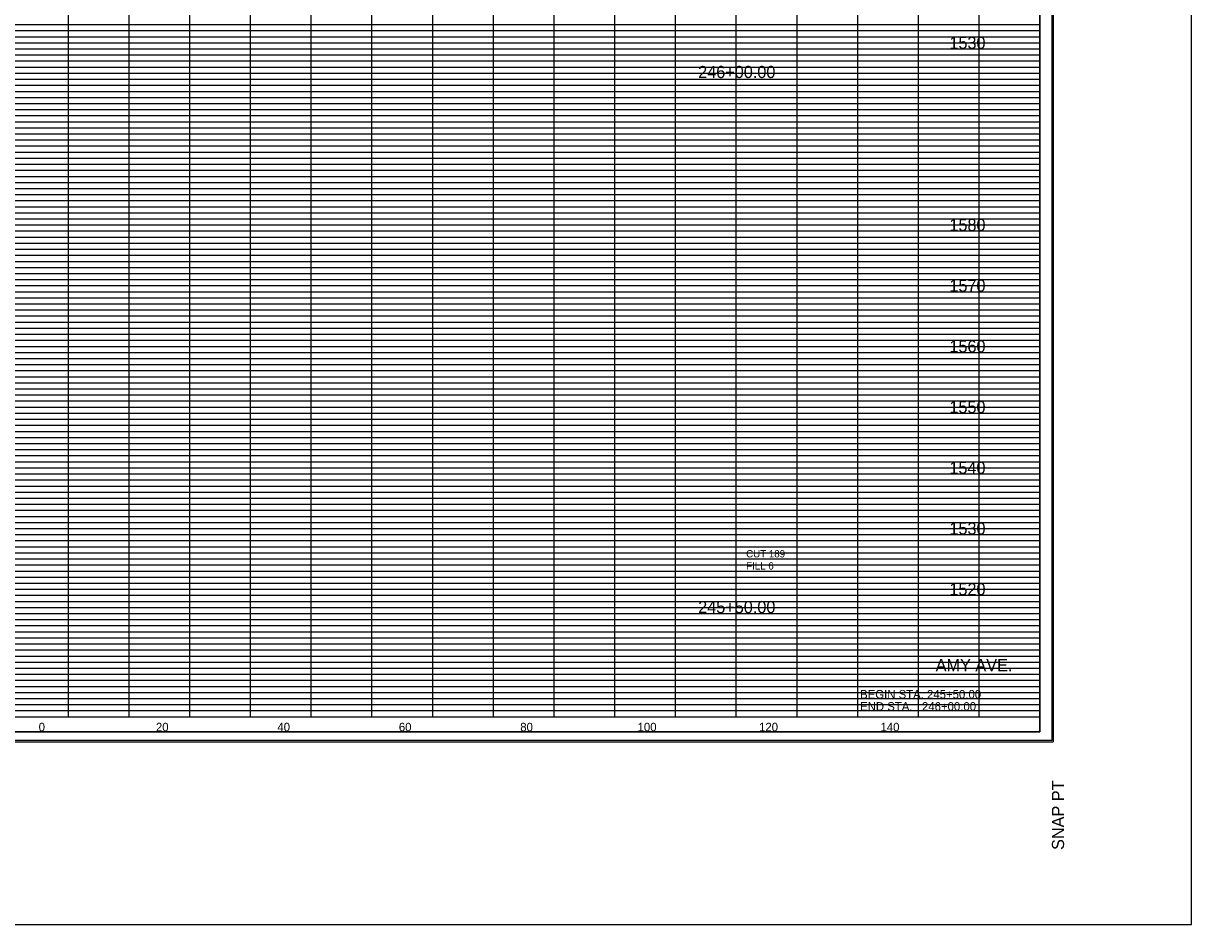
# Model space of a CAD drawing. Extents: x 955 to 1375, y 1248 to 3657.
# Drawn here: x 1152.6 to 1345, y 1505.8 to 1654.2 of the extents above; entities that cross this region are included whole.
import ezdxf

# ---------------------------------------------------------------- set-up
doc = ezdxf.new("R2010")
doc.units = 0
for name, color, linetype in [('DESIGN - SHEET - Corner Text', 7, 'Continuous'), ('DESIGN - SHEET - Light Grid', 7, 'Continuous'), ('DESIGN - SHEET - Linework', 7, 'Continuous'), ('DESIGN - SHEET - Plot Shape', 7, 'Continuous'), ('DESIGN - TYPICAL - Text', 7, 'Continuous'), ('DESIGN - UTILITIES - Cable (Overhead) with Text', 7, 'Continuous'), ('SURVEY - NON-TRANSPORTATION - Features Text', 7, 'Continuous')]:
    doc.layers.add(name, color=color, linetype=linetype)

# ---------------------------------------------------------------- blocks, each defined once
blk = doc.blocks.new('XSTSHT')
at = {"layer": 'DESIGN - SHEET - Light Grid'}
for p, q in [((8, 11.4), (16, 11.4)), ((16, 11.4), (24, 11.4)), ((24, 11.4), (32, 11.4)), ((8, 11.3), (16, 11.3)), ((8, 11.2), (16, 11.2)), ((16, 11.3), (24, 11.3)), ((16, 11.2), (24, 11.2)), ((24, 11.3), (32, 11.3)), ((24, 11.2), (32, 11.2)), ((8, 11.1), (16, 11.1)), ((16, 11.1), (24, 11.1)), ((24, 11.1), (32, 11.1)), ((8, 10.9), (16, 10.9)), ((8, 10.8), (16, 10.8)), ((16, 10.9), (24, 10.9)), ((16, 10.8), (24, 10.8)), ((24, 10.9), (32, 10.9)), ((24, 10.8), (32, 10.8)), ((8, 10.7), (16, 10.7)), ((8, 10.6), (16, 10.6)), ((16, 10.7), (24, 10.7)), ((16, 10.6), (24, 10.6)), ((24, 10.7), (32, 10.7)), ((24, 10.6), (32, 10.6)), ((8, 10.5), (16, 10.5)), ((8, 10.4), (16, 10.4)), ((16, 10.5), (24, 10.5)), ((16, 10.4), (24, 10.4)), ((24, 10.5), (32, 10.5)), ((24, 10.4), (32, 10.4)), ((8, 10.3), (16, 10.3)), ((8, 10.2), (16, 10.2)), ((16, 10.3), (24, 10.3)), ((16, 10.2), (24, 10.2)), ((24, 10.3), (32, 10.3)), ((24, 10.2), (32, 10.2)), ((8, 10.1), (16, 10.1)), ((16, 10.1), (24, 10.1)), ((24, 10.1), (32, 10.1)), ((8, 9.9), (16, 9.9)), ((16, 9.9), (24, 9.9)), ((24, 9.9), (32, 9.9)), ((8, 9.8), (16, 9.8)), ((8, 9.7), (16, 9.7)), ((16, 9.8), (24, 9.8)), ((16, 9.7), (24, 9.7)), ((24, 9.8), (32, 9.8)), ((24, 9.7), (32, 9.7)), ((8, 9.6), (16, 9.6)), ((8, 9.5), (16, 9.5)), ((16, 9.6), (24, 9.6)), ((16, 9.5), (24, 9.5)), ((24, 9.6), (32, 9.6)), ((24, 9.5), (32, 9.5)), ((8, 9.4), (16, 9.4)), ((8, 9.3), (16, 9.3)), ((16, 9.4), (24, 9.4)), ((16, 9.3), (24, 9.3)), ((24, 9.4), (32, 9.4)), ((24, 9.3), (32, 9.3)), ((8, 9.2), (16, 9.2)), ((8, 9.1), (16, 9.1)), ((16, 9.2), (24, 9.2)), ((16, 9.1), (24, 9.1)), ((24, 9.2), (32, 9.2)), ((24, 9.1), (32, 9.1)), ((8, 8.9), (16, 8.9)), ((16, 8.9), (24, 8.9)), ((24, 8.9), (32, 8.9)), ((8, 8.8), (16, 8.8)), ((8, 8.7), (16, 8.7)), ((16, 8.8), (24, 8.8)), ((16, 8.7), (24, 8.7)), ((24, 8.8), (32, 8.8)), ((24, 8.7), (32, 8.7)), ((8, 8.6), (16, 8.6)), ((8, 8.5), (16, 8.5)), ((16, 8.6), (24, 8.6)), ((16, 8.5), (24, 8.5)), ((24, 8.6), (32, 8.6)), ((24, 8.5), (32, 8.5)), ((8, 8.4), (16, 8.4)), ((8, 8.3), (16, 8.3)), ((16, 8.4), (24, 8.4)), ((16, 8.3), (24, 8.3)), ((24, 8.4), (32, 8.4)), ((24, 8.3), (32, 8.3)), ((8, 8.2), (16, 8.2)), ((8, 8.1), (16, 8.1)), ((16, 8.2), (24, 8.2)), ((16, 8.1), (24, 8.1)), ((24, 8.2), (32, 8.2)), ((24, 8.1), (32, 8.1)), ((8, 7.9), (16, 7.9)), ((16, 7.9), (24, 7.9)), ((24, 7.9), (32, 7.9)), ((8, 7.8), (16, 7.8)), ((8, 7.7), (16, 7.7)), ((16, 7.8), (24, 7.8)), ((16, 7.7), (24, 7.7)), ((24, 7.8), (32, 7.8)), ((24, 7.7), (32, 7.7)), ((8, 7.6), (16, 7.6)), ((16, 7.6), (24, 7.6)), ((24, 7.6), (32, 7.6)), ((8, 7.5), (16, 7.5)), ((8, 7.4), (16, 7.4)), ((16, 7.5), (24, 7.5)), ((16, 7.4), (24, 7.4)), ((24, 7.5), (32, 7.5)), ((24, 7.4), (32, 7.4)), ((8, 7.3), (16, 7.3)), ((8, 7.2), (16, 7.2)), ((16, 7.3), (24, 7.3)), ((16, 7.2), (24, 7.2)), ((24, 7.3), (32, 7.3)), ((24, 7.2), (32, 7.2)), ((8, 7.1), (16, 7.1)), ((16, 7.1), (24, 7.1)), ((24, 7.1), (32, 7.1)), ((8, 6.9), (16, 6.9)), ((8, 6.8), (16, 6.8)), ((16, 6.9), (24, 6.9)), ((16, 6.8), (24, 6.8)), ((24, 6.9), (32, 6.9)), ((24, 6.8), (32, 6.8)), ((8, 6.7), (16, 6.7)), ((8, 6.6), (16, 6.6)), ((16, 6.7), (24, 6.7)), ((16, 6.6), (24, 6.6)), ((24, 6.7), (32, 6.7)), ((24, 6.6), (32, 6.6)), ((8, 6.5), (16, 6.5)), ((8, 6.4), (16, 6.4)), ((16, 6.5), (24, 6.5)), ((16, 6.4), (24, 6.4)), ((24, 6.5), (32, 6.5)), ((24, 6.4), (32, 6.4)), ((8, 6.3), (16, 6.3)), ((8, 6.2), (16, 6.2)), ((16, 6.3), (24, 6.3)), ((16, 6.2), (24, 6.2)), ((24, 6.3), (32, 6.3)), ((24, 6.2), (32, 6.2)), ((8, 6.1), (16, 6.1)), ((16, 6.1), (24, 6.1)), ((24, 6.1), (32, 6.1)), ((8, 5.9), (16, 5.9)), ((8, 5.8), (16, 5.8)), ((16, 5.9), (24, 5.9)), ((16, 5.8), (24, 5.8)), ((24, 5.9), (32, 5.9)), ((24, 5.8), (32, 5.8)), ((8, 5.7), (16, 5.7)), ((8, 5.6), (16, 5.6)), ((16, 5.7), (24, 5.7)), ((16, 5.6), (24, 5.6)), ((24, 5.7), (32, 5.7)), ((24, 5.6), (32, 5.6)), ((8, 5.5), (16, 5.5)), ((8, 5.4), (16, 5.4)), ((16, 5.5), (24, 5.5)), ((16, 5.4), (24, 5.4)), ((24, 5.5), (32, 5.5)), ((24, 5.4), (32, 5.4)), ((8, 5.3), (16, 5.3)), ((8, 5.2), (16, 5.2)), ((16, 5.3), (24, 5.3)), ((16, 5.2), (24, 5.2)), ((24, 5.3), (32, 5.3)), ((24, 5.2), (32, 5.2)), ((8, 5.1), (16, 5.1)), ((16, 5.1), (24, 5.1)), ((24, 5.1), (32, 5.1)), ((8, 4.9), (16, 4.9)), ((16, 4.9), (24, 4.9)), ((24, 4.9), (32, 4.9)), ((8, 4.8), (16, 4.8)), ((8, 4.7), (16, 4.7)), ((16, 4.8), (24, 4.8)), ((16, 4.7), (24, 4.7)), ((24, 4.8), (32, 4.8)), ((24, 4.7), (32, 4.7)), ((8, 4.6), (16, 4.6)), ((8, 4.5), (16, 4.5)), ((16, 4.6), (24, 4.6)), ((16, 4.5), (24, 4.5)), ((24, 4.6), (32, 4.6)), ((24, 4.5), (32, 4.5)), ((8, 4.4), (16, 4.4)), ((8, 4.3), (16, 4.3)), ((16, 4.4), (24, 4.4)), ((16, 4.3), (24, 4.3)), ((24, 4.4), (32, 4.4)), ((24, 4.3), (32, 4.3)), ((8, 4.2), (16, 4.2)), ((8, 4.1), (16, 4.1)), ((16, 4.2), (24, 4.2)), ((16, 4.1), (24, 4.1)), ((24, 4.2), (32, 4.2)), ((24, 4.1), (32, 4.1)), ((8, 3.9), (16, 3.9)), ((16, 3.9), (24, 3.9)), ((24, 3.9), (32, 3.9)), ((8, 3.8), (16, 3.8)), ((8, 3.7), (16, 3.7)), ((16, 3.8), (24, 3.8)), ((16, 3.7), (24, 3.7)), ((24, 3.8), (32, 3.8)), ((24, 3.7), (32, 3.7)), ((8, 3.6), (16, 3.6)), ((8, 3.5), (16, 3.5)), ((16, 3.6), (24, 3.6)), ((16, 3.5), (24, 3.5)), ((24, 3.6), (32, 3.6)), ((24, 3.5), (32, 3.5)), ((8, 3.4), (16, 3.4)), ((8, 3.3), (16, 3.3)), ((16, 3.4), (24, 3.4)), ((16, 3.3), (24, 3.3)), ((24, 3.4), (32, 3.4)), ((24, 3.3), (32, 3.3)), ((8, 3.2), (16, 3.2)), ((8, 3.1), (16, 3.1)), ((16, 3.2), (24, 3.2)), ((16, 3.1), (24, 3.1)), ((24, 3.2), (32, 3.2)), ((24, 3.1), (32, 3.1)), ((8, 2.9), (16, 2.9)), ((16, 2.9), (24, 2.9)), ((24, 2.9), (32, 2.9)), ((8, 2.8), (16, 2.8)), ((8, 2.7), (16, 2.7)), ((16, 2.8), (24, 2.8)), ((16, 2.7), (24, 2.7)), ((24, 2.8), (32, 2.8)), ((24, 2.7), (32, 2.7)), ((8, 2.6), (16, 2.6)), ((16, 2.6), (24, 2.6)), ((24, 2.6), (32, 2.6)), ((8, 2.5), (16, 2.5)), ((8, 2.4), (16, 2.4)), ((16, 2.5), (24, 2.5)), ((16, 2.4), (24, 2.4)), ((24, 2.5), (32, 2.5)), ((24, 2.4), (32, 2.4)), ((8, 2.3), (16, 2.3)), ((8, 2.2), (16, 2.2)), ((16, 2.3), (24, 2.3)), ((16, 2.2), (24, 2.2)), ((24, 2.3), (32, 2.3)), ((24, 2.2), (32, 2.2)), ((8, 2.1), (16, 2.1)), ((16, 2.1), (24, 2.1)), ((24, 2.1), (32, 2.1)), ((8, 1.9), (16, 1.9)), ((8, 1.8), (16, 1.8)), ((16, 1.9), (24, 1.9)), ((16, 1.8), (24, 1.8)), ((24, 1.9), (32, 1.9)), ((24, 1.8), (32, 1.8)), ((8, 1.7), (16, 1.7)), ((8, 1.6), (16, 1.6)), ((16, 1.7), (24, 1.7)), ((16, 1.6), (24, 1.6)), ((24, 1.7), (32, 1.7)), ((24, 1.6), (32, 1.6)), ((8, 1.5), (16, 1.5)), ((8, 1.4), (16, 1.4)), ((16, 1.5), (24, 1.5)), ((16, 1.4), (24, 1.4)), ((24, 1.5), (32, 1.5)), ((24, 1.4), (32, 1.4)), ((8, 1.3), (16, 1.3)), ((8, 1.2), (16, 1.2)), ((16, 1.3), (24, 1.3)), ((16, 1.2), (24, 1.2)), ((24, 1.3), (32, 1.3)), ((24, 1.2), (32, 1.2)), ((8, 1.1), (16, 1.1)), ((16, 1.1), (24, 1.1)), ((24, 1.1), (32, 1.1)), ((8, 0.9), (16, 0.9)), ((8, 0.8), (16, 0.8)), ((16, 0.9), (24, 0.9)), ((16, 0.8), (24, 0.8)), ((24, 0.9), (32, 0.9)), ((24, 0.8), (32, 0.8)), ((8, 0.7), (16, 0.7)), ((8, 0.6), (16, 0.6)), ((16, 0.7), (24, 0.7)), ((16, 0.6), (24, 0.6)), ((24, 0.7), (32, 0.7)), ((24, 0.6), (32, 0.6)), ((8, 0.5), (16, 0.5)), ((8, 0.4), (16, 0.4)), ((16, 0.5), (24, 0.5)), ((16, 0.4), (24, 0.4)), ((24, 0.5), (32, 0.5)), ((24, 0.4), (32, 0.4)), ((8, 0.3), (16, 0.3)), ((8, 0.2), (16, 0.2)), ((16, 0.3), (24, 0.3)), ((16, 0.2), (24, 0.2)), ((24, 0.3), (32, 0.3)), ((24, 0.2), (32, 0.2)), ((8, 0.1), (16, 0.1)), ((16, 0.1), (24, 0.1)), ((24, 0.1), (32, 0.1))]:
    blk.add_line(p, q, dxfattribs=at)
at = {"layer": 'DESIGN - SHEET - Linework'}
for p, q in [((32.217, 21.414), (32.217, -0.414)), ((16, 0), (16, 21)), ((17, 0), (17, 21)), ((18, 0), (18, 21)), ((19, 0), (19, 21)), ((20, 0), (20, 21)), ((21, 0), (21, 21)), ((22, 0), (22, 21)), ((23, 0), (23, 21)), ((24, 0), (24, 21)), ((25, 0), (25, 21)), ((26, 0), (26, 21)), ((27, 0), (27, 21)), ((28, 0), (28, 20)), ((29, 0), (29, 20)), ((30, 0), (30, 20)), ((31, 0), (31, 20)), ((0, 11), (32, 11)), ((0, 10), (32, 10)), ((0, 9), (32, 9)), ((0, 8), (32, 8)), ((0, 7), (32, 7)), ((0, 6), (32, 6)), ((0, 5), (32, 5)), ((0, 4), (32, 4)), ((0, 3), (32, 3)), ((0, 2), (32, 2)), ((0, 1), (32, 1)), ((-1.823, -0.414), (32.217, -0.414))]:
    blk.add_line(p, q, dxfattribs=at)
blk.add_lwpolyline([(0, 21), (0, 0), (32, 0), (32, 21), (0, 21)], dxfattribs=at)
at = {"layer": 'DESIGN - SHEET - Plot Shape'}
for points in [[(-1.803, 21.394), (32.197, 21.394), (32.197, -0.394), (-1.803, -0.394)], [(-0.85, 21), (32, 21), (32, -0.25), (-0.85, -0.25)]]:
    blk.add_lwpolyline(points, close=True, dxfattribs=at)
at = {"layer": 'DESIGN - SHEET - Corner Text'}
blk.add_text('SNAP PT  ', height=0.2, rotation=90, dxfattribs=at).set_placement((32.397, -2.194))

msp = doc.modelspace()

# ---------------------------------------------------------------- linework, layer by layer
at = {"layer": 'DESIGN - SHEET - Plot Shape'}
msp.add_lwpolyline([(991.5, 1537.5), (1320, 1537.5), (1320, 1750), (991.5, 1750)], close=True, dxfattribs=at)
at = {"layer": 'SURVEY - NON-TRANSPORTATION - Features Text'}
msp.add_lwpolyline([(955.41, 1505.76), (1344.98, 1505.76), (1344.98, 3398.01), (955.41, 3398.01)], close=True, dxfattribs=at)

# ---------------------------------------------------------------- block references
at = {"layer": 'DESIGN - UTILITIES - Cable (Overhead) with Text', "xscale": 10, "yscale": 10}
msp.add_blockref('XSTSHT', (1000, 1540), dxfattribs=at)

# ---------------------------------------------------------------- texts
at = {"layer": 'DESIGN - SHEET - Corner Text'}
for s, height, p in [('AMY AVE.', 2, (1302.83, 1547.5)), ('BEGIN STA. 245+50.00', 1.4, (1290.38, 1543)), ('END STA.   246+00.00', 1.4, (1290.38, 1541))]:
    msp.add_text(s, height=height, dxfattribs=at).set_placement(p)
at = {"layer": 'DESIGN - TYPICAL - Text'}
for s, height, p in [('     1530     ', 2, (1301.37, 1650)), ('     246+00.00     ', 2, (1260, 1645.19)), ('     1580     ', 2, (1301.37, 1620)), ('     1570     ', 2, (1301.37, 1610)), ('     1560     ', 2, (1301.37, 1600)), ('     1550     ', 2, (1301.37, 1590)), ('     1540     ', 2, (1301.37, 1580)), ('     1530     ', 2, (1301.37, 1570)), ('CUT 189', 1.2, (1271.61, 1566.24)), ('FILL 6', 1.2, (1271.61, 1564.24)), ('     1520     ', 2, (1301.37, 1560)), ('     245+50.00     ', 2, (1260, 1557.06)), ('     0     ', 1.4, (1152.51, 1537.6)), ('     0     ', 1.4, (1152.51, 1537.6)), ('     20     ', 1.4, (1171.82, 1537.6)), ('     40     ', 1.4, (1191.82, 1537.6)), ('     60     ', 1.4, (1211.82, 1537.6)), ('     80     ', 1.4, (1231.82, 1537.6)), ('     100     ', 1.4, (1251.14, 1537.6)), ('     120     ', 1.4, (1271.14, 1537.6)), ('     140     ', 1.4, (1291.14, 1537.6))]:
    msp.add_text(s, height=height, dxfattribs=at).set_placement(p)

doc.saveas('drawing.dxf')
